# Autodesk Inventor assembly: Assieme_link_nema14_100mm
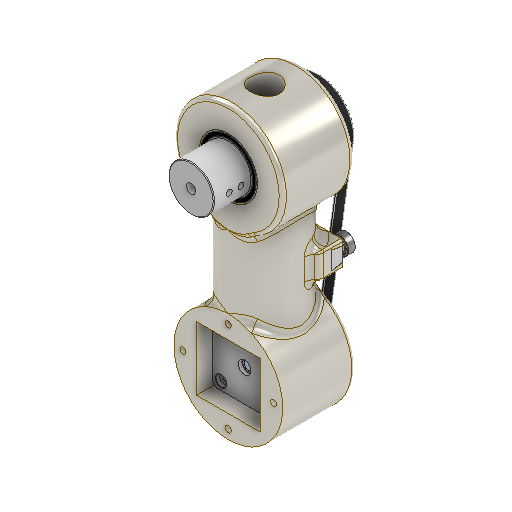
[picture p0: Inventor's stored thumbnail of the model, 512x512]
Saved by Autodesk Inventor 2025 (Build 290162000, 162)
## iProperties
Created: 2025-05
Part Number: Assieme_link_nema14_100mm
Document SubType Name: Assembly
Designer: 18907419
Author: 18907419
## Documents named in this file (9)
- C:\Users\R5800u\Desktop\robot v3\Assieme_link_nema14_100mm.iam
- C:\Users\R5800u\Desktop\robot v3\NEMA_14-13mm.iam
- C:\Users\R5800u\Desktop\robot v3\blocco3.ipt
- C:\Users\R5800u\Desktop\robot v3\gt2-60.ipt
- C:\Users\R5800u\Desktop\robot v3\cinghia.ipt
- C:\Users\R5800u\Desktop\robot v3\blocco_tendi.ipt
- C:\Users\R5800u\Documents\Inventor\Content Center Files\R2025\it-IT\BS 290 SKF(30)\BS 290 SKF - SKF 623.ipt
- C:\Users\R5800u\Desktop\robot v3\6705-2RS.ipt
- C:\Users\R5800u\Documents\Inventor\Content Center Files\R2025\it-IT\AS 1420\AS 1420 - 1973 - M3 x 6.ipt
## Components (9 placed, 8 different names)
1. blocco3:2 — Coincidente:64, Allineato:11, Coincidente:65, Coincidente:66, Coincidente:67, Allineato:14, Rotazionale:25, Rotazionale:26, Coincidente:74, Rigido:1, Angolo:1
2. NEMA_14HM11-0404S:4 [sub-assembly] — Coincidente:66, Coincidente:67, Coincidente:73, Allineato:15
3. cinghia:1 — Coincidente:73, Coincidente:76, Allineato:16
4. blocco_tendi:1 — Allineato:14, Rigido:1, Rotazionale:27
5. 6705-2RS:3 — Rotazionale:25
6. 6705-2RS:4 — Rotazionale:26, Coincidente:75
7. gt2-60:1 — Coincidente:74, Coincidente:75, Allineato:15, Coincidente:76, Angolo:1, Allineato:16
8. BS 290 SKF 623:1 — Rotazionale:27
9. AS 1420 - Metrico M3 x 6:1
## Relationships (17: Mate 8, Flush 4, RevoluteJoint 3, WeldJoint 1, Angle 1)
- Coincidente:64 [Mate]: blocco3:2
- Allineato:11 [Flush]: blocco3:2
- Coincidente:65 [Mate]: blocco3:2
- Coincidente:66 [Mate]: blocco3:2 ↔ NEMA_14HM11-0404S:4
- Coincidente:67 [Mate]: blocco3:2 ↔ NEMA_14HM11-0404S:4
- Allineato:14 [Flush]: blocco3:2 ↔ blocco_tendi:1
- Rotazionale:25 [RevoluteJoint]: blocco3:2 ↔ 6705-2RS:3
- Coincidente:73 [Mate]: NEMA_14HM11-0404S:4 ↔ cinghia:1
- Rotazionale:26 [RevoluteJoint]: blocco3:2 ↔ 6705-2RS:4
- Coincidente:74 [Mate]: blocco3:2 ↔ gt2-60:1
- Coincidente:75 [Mate]: 6705-2RS:4 ↔ gt2-60:1
- Allineato:15 [Flush]: NEMA_14HM11-0404S:4 ↔ gt2-60:1
- Coincidente:76 [Mate]: cinghia:1 ↔ gt2-60:1
- Rigido:1 [WeldJoint]: blocco3:2 ↔ blocco_tendi:1
- Angolo:1 [Angle]: blocco3:2 ↔ gt2-60:1
- Allineato:16 [Flush]: cinghia:1 ↔ gt2-60:1
- Rotazionale:27 [RevoluteJoint]: blocco_tendi:1 ↔ BS 290 SKF 623:1
